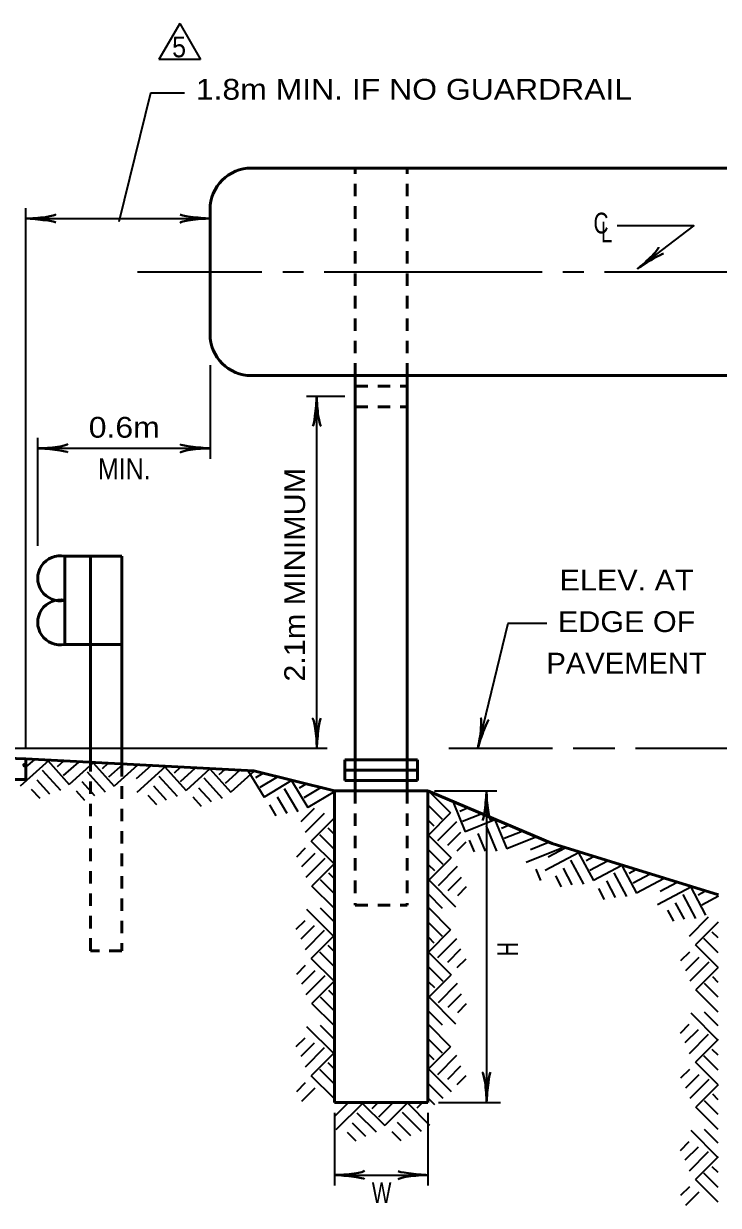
# Model space of a CAD drawing. Extents: x -27 to 828, y -12 to 532.
# Drawn here: x 138.5 to 218.8, y 94.8 to 231.4 of the extents above; entities that cross this region are included whole.
import ezdxf
from ezdxf.enums import TextEntityAlignment as Align

# ---------------------------------------------------------------- set-up
doc = ezdxf.new("R2010")
doc.units = 0
doc.header["$LTSCALE"] = 0.96
doc.linetypes.add('SHORT_DASHED', pattern=[2.7, 1.5, -1.2])
doc.layers.add('1', color=7, linetype='Continuous', lineweight=35)

msp = doc.modelspace()

# ---------------------------------------------------------------- linework, layer by layer
at = {"layer": '1'}
for p, q in [((156.5064, 231.4008), (154.1064, 227.2439)), ((156.5064, 231.4008), (158.9064, 227.2439)), ((158.9064, 227.2439), (154.1064, 227.2439)), ((138.7294, 147.6739), (138.7294, 210.0739)), ((138.7294, 208.8739), (160.008, 208.8739)), ((151.608, 202.7133), (166.008, 202.7133)), ((168.408, 202.7133), (170.808, 202.7133)), ((173.208, 202.7133), (198.408, 202.7133)), ((200.808, 202.7133), (203.208, 202.7133)), ((205.608, 202.7133), (230.808, 202.7133)), ((160.008, 191.9133), (160.008, 181.1133)), ((175.608, 188.3133), (171.1513, 188.3133)), ((172.3513, 147.6739), (172.3513, 188.3133)), ((140.1198, 171.0369), (140.1198, 183.5133)), ((140.1198, 182.3133), (160.008, 182.3133)), ((111.1513, 147.6739), (173.5513, 147.6739)), ((187.608, 147.6739), (199.608, 147.6739)), ((202.008, 147.6739), (206.808, 147.6739)), ((209.208, 147.6739), (221.208, 147.6739)), ((141.3633, 146.2314), (138.059, 143.2563)), ((139.6616, 146.3206), (138.7294, 145.4812)), ((141.2434, 146.2377), (143.7416, 143.4631)), ((140.6079, 145.1174), (142.7213, 142.7956)), ((143.0649, 146.1422), (142.3574, 145.4823)), ((144.7905, 146.0518), (143.0501, 144.4847)), ((146.4922, 145.9626), (143.7416, 143.4631)), ((145.8125, 144.9167), (147.902, 142.5962)), ((146.4922, 145.9626), (148.9223, 143.2637)), ((148.1939, 145.8734), (147.5381, 145.2829)), ((149.9195, 145.783), (148.2548, 144.284)), ((151.6212, 145.6938), (148.9223, 143.2637)), ((153.1551, 145.6134), (151.4903, 144.1145)), ((154.8567, 145.5242), (151.5525, 142.5491)), ((154.7369, 145.5305), (157.2351, 142.7559)), ((156.5584, 145.435), (155.8509, 144.7752)), ((158.284, 145.3446), (156.5436, 143.7775)), ((159.9857, 145.2554), (157.2351, 142.7559)), ((159.9857, 145.2554), (162.4158, 142.5565)), ((161.6874, 145.1662), (161.0316, 144.5757)), ((163.413, 145.0758), (161.7483, 143.5769)), ((165.1147, 144.9866), (162.4158, 142.5565)), ((164.3982, 145.0722), (166.2593, 141.9748)), ((139.9964, 143.9959), (141.4499, 142.3816)), ((145.201, 143.7952), (146.6545, 142.1809)), ((154.1014, 144.4102), (156.2148, 142.0884)), ((159.306, 144.2096), (161.3954, 141.889)), ((166.1062, 144.7338), (165.2858, 144.221)), ((167.7829, 144.3157), (165.7754, 143.1095)), ((169.4362, 143.9035), (166.2593, 141.9748)), ((169.4362, 143.9035), (171.3067, 140.7905)), ((171.0896, 143.4912), (170.3332, 143.0367)), ((139.3394, 142.9248), (140.3172, 141.8642)), ((144.5201, 142.7254), (145.4967, 141.6408)), ((152.8329, 142.2176), (153.8107, 141.157)), ((153.4899, 143.2887), (154.9434, 141.6744)), ((158.6945, 143.088), (160.148, 141.4737)), ((168.5695, 143.0065), (170.1777, 140.3299)), ((172.7663, 143.0732), (170.8461, 141.9194)), ((174.4197, 142.6609), (171.3067, 140.7905)), ((185.256, 142.7373), (187.824, 140.1693)), ((185.9784, 142.7385), (193.1784, 142.7385)), ((191.9784, 142.7385), (191.9784, 106.7385)), ((158.0136, 142.0182), (158.9901, 140.9336)), ((166.8826, 141.102), (167.6343, 139.851)), ((167.7552, 142.0223), (168.874, 140.1603)), ((185.256, 141.0333), (186.84, 139.4493)), ((188.1054, 141.4313), (189.504, 137.9696)), ((189.7844, 140.7186), (188.8939, 140.3405)), ((172.056, 140.6733), (170.52, 139.1373)), ((173.208, 140.1213), (171, 137.8893)), ((174.36, 139.5453), (171.72, 136.9053)), ((185.256, 137.6013), (187.824, 140.1693)), ((191.375, 140.0434), (189.2036, 139.1661)), ((192.9436, 139.3776), (189.504, 137.9696)), ((192.9436, 139.3776), (194.304, 136.0104)), ((174.36, 137.7213), (173.664, 138.3933)), ((185.256, 139.3053), (185.88, 138.6813)), ((186.336, 136.9773), (188.544, 139.1853)), ((187.488, 136.4253), (189.024, 137.9613)), ((191.9472, 138.6273), (193.1169, 135.7321)), ((194.5121, 138.7118), (193.6939, 138.3812)), ((196.1028, 138.0366), (194.0258, 137.1975)), ((174.36, 134.2893), (171.72, 136.9053)), ((174.36, 135.9933), (172.704, 137.6493)), ((185.256, 137.6013), (187.896, 134.9853)), ((188.592, 135.8013), (189.624, 136.8333)), ((189.9832, 137.0101), (190.5299, 135.6569)), ((190.989, 137.7825), (191.8027, 135.7685)), ((197.6713, 137.3708), (194.304, 136.0104)), ((199.1294, 136.7519), (197.0524, 135.9127)), ((171.024, 136.0893), (169.992, 135.0573)), ((172.128, 135.4653), (170.592, 133.9293)), ((185.256, 135.8973), (186.912, 134.2413)), ((200.6979, 136.0861), (196.5754, 134.4205)), ((202.6971, 135.6074), (198.7691, 133.5241)), ((201.0681, 136.1073), (199.0891, 135.0577)), ((202.5824, 135.6426), (204.3317, 132.3442)), ((173.28, 134.9133), (171.072, 132.7053)), ((174.36, 134.2893), (171.792, 131.7213)), ((185.256, 132.3453), (187.896, 134.9853)), ((185.256, 134.1693), (185.952, 133.4973)), ((186.408, 131.7693), (188.616, 134.0013)), ((201.6938, 134.7103), (203.1798, 131.9446)), ((204.3261, 135.1074), (203.4795, 134.6392)), ((205.9781, 134.6005), (203.9091, 133.5032)), ((207.6071, 134.1005), (204.3317, 132.3442)), ((207.6071, 134.1005), (209.3087, 130.8921)), ((174.36, 132.5853), (173.736, 133.2093)), ((187.56, 131.2173), (189.096, 132.7533)), ((197.6652, 133.6711), (198.2213, 132.34)), ((199.9306, 132.8915), (200.6214, 131.6251)), ((200.8281, 133.7709), (201.8459, 131.8518)), ((206.6937, 133.2511), (208.1568, 130.4925)), ((209.2361, 133.6006), (208.4565, 133.1871)), ((210.8881, 133.0936), (208.9091, 132.0441)), ((212.5171, 132.5937), (209.3087, 130.8921)), ((174.36, 129.1533), (171.792, 131.7213)), ((174.36, 130.8573), (172.776, 132.4413)), ((185.256, 132.4653), (188.4, 129.3213)), ((188.664, 130.6173), (189.672, 131.6493)), ((204.9076, 131.4394), (205.5914, 130.1501)), ((205.828, 132.3118), (206.8458, 130.3927)), ((215.6604, 131.6291), (211.7324, 129.5458)), ((214.0314, 132.129), (212.0524, 131.0794)), ((215.5457, 131.6643), (217.295, 128.3659)), ((217.2894, 131.1291), (216.4428, 130.6609)), ((185.256, 130.7613), (186.84, 129.1773)), ((213.7914, 129.7926), (214.8091, 127.8735)), ((214.6571, 130.7319), (216.143, 127.9663)), ((218.808, 130.5515), (216.8724, 129.5249)), ((174.36, 125.8653), (171.216, 129.0093)), ((174.36, 127.5693), (172.776, 129.1533)), ((185.256, 129.2253), (187.824, 126.6573)), ((212.8939, 128.9132), (213.5847, 127.6468)), ((170.952, 127.7133), (169.944, 126.6813)), ((172.056, 127.1133), (170.52, 125.5773)), ((185.256, 127.5213), (186.84, 125.9373)), ((217.608, 128.1213), (215.4, 125.8893)), ((218.76, 127.5453), (216.12, 124.9053)), ((173.208, 126.5613), (171, 124.3293)), ((174.36, 125.9853), (171.72, 123.3453)), ((185.256, 124.0893), (187.824, 126.6573)), ((185.256, 125.7933), (185.88, 125.1693)), ((186.336, 123.4653), (188.544, 125.6733)), ((218.76, 125.7213), (218.064, 126.3933)), ((174.36, 124.1613), (173.664, 124.8333)), ((187.488, 122.9133), (189.024, 124.4493)), ((218.76, 122.2893), (216.12, 124.9053)), ((218.76, 123.9933), (217.104, 125.6493)), ((174.36, 120.7293), (171.72, 123.3453)), ((174.36, 122.4333), (172.704, 124.0893)), ((185.256, 124.0893), (187.896, 121.4733)), ((188.592, 122.2893), (189.624, 123.3213)), ((215.424, 124.0893), (214.392, 123.0573)), ((216.528, 123.4653), (214.992, 121.9293)), ((171.024, 122.5293), (169.992, 121.4973)), ((172.128, 121.9053), (170.592, 120.3693)), ((185.256, 122.3853), (186.912, 120.7293)), ((217.68, 122.9133), (215.472, 120.7053)), ((218.76, 122.2893), (216.192, 119.7213)), ((173.28, 121.3533), (171.072, 119.1453)), ((174.36, 120.7293), (171.792, 118.1613)), ((185.256, 118.8333), (187.896, 121.4733)), ((185.256, 120.6573), (185.952, 119.9853)), ((186.408, 118.2573), (188.616, 120.4893)), ((218.76, 118.8573), (217.176, 120.4413)), ((218.76, 120.5853), (218.136, 121.2093)), ((174.36, 117.2973), (172.776, 118.8813)), ((174.36, 119.0253), (173.736, 119.6493)), ((185.256, 118.9533), (188.4, 115.8093)), ((187.56, 117.7053), (189.096, 119.2413)), ((218.76, 117.1533), (216.192, 119.7213)), ((174.36, 115.5933), (171.792, 118.1613)), ((188.664, 117.1053), (189.672, 118.1373)), ((185.256, 117.2493), (186.84, 115.6653)), ((218.76, 113.8653), (215.616, 117.0093)), ((218.76, 115.5693), (217.176, 117.1533)), ((174.36, 112.3053), (171.216, 115.4493)), ((174.36, 114.0093), (172.776, 115.5933)), ((185.256, 115.7133), (187.824, 113.1453)), ((215.352, 115.7133), (214.344, 114.6813)), ((216.456, 115.1133), (214.92, 113.5773)), ((170.952, 114.1533), (169.944, 113.1213)), ((172.056, 113.5533), (170.52, 112.0173)), ((185.256, 114.0093), (186.84, 112.4253)), ((217.608, 114.5613), (215.4, 112.3293)), ((218.76, 113.9853), (216.12, 111.3453)), ((173.208, 113.0013), (171, 110.7693)), ((174.36, 112.4253), (171.72, 109.7853)), ((185.256, 110.5773), (187.824, 113.1453)), ((185.256, 112.2813), (185.88, 111.6573)), ((186.336, 109.9533), (188.544, 112.1613)), ((218.76, 110.4333), (217.104, 112.0893)), ((218.76, 112.1613), (218.064, 112.8333)), ((174.36, 110.6013), (173.664, 111.2733)), ((187.488, 109.4013), (189.024, 110.9373)), ((218.76, 108.7293), (216.12, 111.3453)), ((174.36, 107.1693), (171.72, 109.7853)), ((174.36, 108.8733), (172.704, 110.5293)), ((185.256, 110.5773), (187.896, 107.9613)), ((188.592, 108.7773), (189.624, 109.8093)), ((215.424, 110.5293), (214.392, 109.4973)), ((216.528, 109.9053), (214.992, 108.3693)), ((217.68, 109.3533), (215.472, 107.1453)), ((171.024, 108.9693), (169.992, 107.9373)), ((172.128, 108.3453), (170.592, 106.8093)), ((185.256, 108.8733), (186.912, 107.2173)), ((218.76, 108.7293), (216.192, 106.1613)), ((175.992, 106.6653), (174.408, 105.0813)), ((177.696, 106.6653), (174.552, 103.5213)), ((177.576, 106.6653), (180.216, 104.0253)), ((179.4, 106.6653), (178.728, 105.9693)), ((181.128, 106.6653), (179.472, 105.0093)), ((182.832, 106.6653), (180.216, 104.0253)), ((182.832, 106.6653), (185.4, 104.0973)), ((184.536, 106.6653), (183.912, 106.0413)), ((185.256, 107.1453), (185.952, 106.4733)), ((186.408, 106.7133), (193.608, 106.7133)), ((218.76, 105.2973), (217.176, 106.8813)), ((218.76, 107.0253), (218.136, 107.6493)), ((174.408, 105.5133), (174.408, 97.1133)), ((177, 105.5133), (179.232, 103.3053)), ((182.208, 105.5853), (184.416, 103.3773)), ((185.208, 105.5133), (185.208, 97.1133)), ((218.76, 103.5933), (216.192, 106.1613)), ((176.448, 104.3613), (177.984, 102.8253)), ((181.656, 104.4333), (183.192, 102.8973)), ((175.848, 103.2573), (176.88, 102.2493)), ((181.032, 103.3293), (182.064, 102.2973)), ((218.76, 100.3053), (215.616, 103.4493)), ((218.76, 102.0093), (217.176, 103.5933)), ((215.352, 102.1533), (214.344, 101.1213)), ((216.456, 101.5533), (214.92, 100.0173)), ((217.608, 101.0013), (215.4, 98.7693)), ((218.76, 100.4253), (216.12, 97.7853)), ((218.76, 96.8733), (217.104, 98.5293)), ((218.76, 98.6013), (218.064, 99.2733)), ((174.408, 98.3133), (185.208, 98.3133)), ((218.76, 95.1693), (216.12, 97.7853)), ((215.424, 96.9693), (214.392, 95.9373)), ((216.528, 96.3453), (214.992, 94.8093))]:
    msp.add_line(p, q, dxfattribs=at)
at = {"layer": '1', "lineweight": 53}
for p, q in [((164.808, 214.7133), (239.208, 214.7133)), ((160.008, 209.9133), (160.008, 195.5133)), ((164.808, 190.7133), (239.208, 190.7133)), ((176.808, 190.7133), (176.808, 142.7133)), ((182.808, 190.7133), (182.808, 142.7133)), ((149.808, 169.8369), (143.208, 169.8369)), ((143.208, 169.8369), (143.208, 159.6369)), ((146.208, 146.0256), (146.208, 169.8369)), ((149.808, 145.8369), (149.808, 169.8369)), ((149.808, 159.6369), (143.208, 159.6369)), ((138.7294, 146.4175), (165.0932, 145.0358)), ((175.608, 146.3133), (184.008, 146.3133)), ((175.608, 146.3133), (175.608, 143.9133)), ((184.008, 146.3133), (184.008, 143.9133)), ((138.7294, 145.7955), (138.7132, 145.8171)), ((165.0932, 145.0358), (174.408, 142.7133)), ((175.608, 145.1133), (184.008, 145.1133)), ((175.608, 143.9133), (184.008, 143.9133)), ((174.408, 142.7133), (185.208, 142.7133)), ((174.408, 142.7133), (174.408, 106.7133)), ((185.208, 142.7133), (185.208, 106.7133)), ((185.208, 142.7133), (199.5679, 136.6179)), ((199.5679, 136.6179), (218.808, 130.7133)), ((174.408, 106.7133), (185.208, 106.7133))]:
    msp.add_line(p, q, dxfattribs=at)
at = {"layer": '1', "linetype": 'SHORT_DASHED', "lineweight": 53}
for p, q in [((176.808, 190.7133), (176.808, 214.7133)), ((182.808, 190.7133), (182.808, 214.7133)), ((176.808, 189.5133), (182.808, 189.5133)), ((176.808, 187.1133), (182.808, 187.1133)), ((176.808, 142.7133), (176.808, 129.5133)), ((182.808, 142.7133), (182.808, 129.5133)), ((176.808, 129.5133), (182.808, 129.5133))]:
    msp.add_line(p, q, dxfattribs=at)
at = {"layer": '1'}
for points in [[(149.5078, 208.5399), (153.1546, 223.3926), (157.062, 223.3926)], [(209.4202, 203.0679), (215.9325, 208.0188), (207.0758, 208.0188)], [(190.9662, 147.6739), (194.4785, 162.0974), (198.9511, 162.0974)]]:
    msp.add_lwpolyline(points, dxfattribs=at)
at = {"layer": '1', "lineweight": 53}
msp.add_lwpolyline([(66.7294, 144.0175), (102.7513, 144.0175), (102.7513, 147.6739), (138.7294, 146.4175), (138.7294, 144.0175), (102.7513, 144.0175), (102.7513, 147.6739), (138.7294, 146.4175), (138.7294, 144.0175), (102.7513, 144.0175)], dxfattribs=at)
at = {"layer": '1', "linetype": 'SHORT_DASHED', "lineweight": 53}
msp.add_lwpolyline([(149.808, 145.8369), (149.808, 124.2369), (146.208, 124.2369), (146.208, 146.0256)], dxfattribs=at)
at = {"layer": '1', "lineweight": 53}
for centre, radius, start, end in [((164.808, 209.9133), 4.8, 90, 180), ((164.808, 195.5133), 4.8, 180, 270), ((142.6946, 167.2869), 2.6012, 78.61588, 281.38413), ((142.6946, 162.1869), 2.6012, 78.61588, 281.38413)]:
    msp.add_arc(centre, radius, start, end, dxfattribs=at)
at = {"layer": '1', "lineweight": 40}
for centre, major_axis, ratio, start_param, end_param in [((140.0388, 209.2055), (-2.1428, -0.1874), 0.122415, 0.89635335, 3.14159265), ((158.6634, 209.1278), (2.1077, -0.2108), 0.07063, 3.14071475, 5.41810995), ((140.074, 208.62), (-2.1077, 0.2108), 0.07063, 3.14071475, 5.41810995), ((158.6986, 208.5423), (2.1428, 0.1874), 0.122415, 0.89635335, 3.14159265), ((210.2619, 204.1243), (-1.5924, -1.446), 0.122415, 0.89635335, 3.14159265), ((210.6443, 203.6795), (-1.8055, -1.1078), 0.07063, 3.14071475, 5.41810995), ((172.0974, 186.9687), (0.2108, 2.1077), 0.07063, 3.14071475, 5.41810995), ((172.6829, 187.0039), (-0.1874, 2.1428), 0.122415, 0.89635335, 3.14159265), ((141.4644, 182.0594), (-2.1077, 0.2108), 0.07063, 3.14071475, 5.41810995), ((141.4292, 182.6449), (-2.1428, -0.1874), 0.122415, 0.89635335, 3.14159265), ((158.6986, 181.9817), (2.1428, 0.1874), 0.122415, 0.89635335, 3.14159265), ((158.6634, 182.5672), (2.1077, -0.2108), 0.07063, 3.14071475, 5.41810995), ((172.0197, 148.9833), (0.1874, -2.1428), 0.122415, 0.89635335, 3.14159265), ((172.6052, 149.0185), (-0.2108, -2.1077), 0.07063, 3.14071475, 5.41810995), ((190.9539, 149.0246), (-0.3249, -2.1263), 0.122415, 0.89635335, 3.14159265), ((191.531, 148.9202), (0.7035, 1.998), 0.07063, 6.28230741, 8.55970261), ((191.7245, 141.3939), (0.2108, 2.1077), 0.07063, 3.14071475, 5.41810995), ((192.31, 141.4291), (-0.1874, 2.1428), 0.122415, 0.89635335, 3.14159265), ((191.6468, 108.0479), (0.1874, -2.1428), 0.122415, 0.89635335, 3.14159265), ((191.6468, 108.0479), (0.1874, -2.1428), 0.122415, 0.89635335, 3.14159265), ((192.2323, 108.0831), (-0.2108, -2.1077), 0.07063, 3.14071475, 5.41810995), ((192.2323, 108.0831), (-0.2108, -2.1077), 0.07063, 3.14071475, 5.41810995), ((175.7174, 98.6449), (-2.1428, -0.1874), 0.122415, 0.89635335, 3.14159265), ((175.7174, 98.6449), (-2.1428, -0.1874), 0.122415, 0.89635335, 3.14159265), ((183.8634, 98.5672), (2.1077, -0.2108), 0.07063, 3.14071475, 5.41810995), ((183.8634, 98.5672), (2.1077, -0.2108), 0.07063, 3.14071475, 5.41810995), ((175.7526, 98.0594), (-2.1077, 0.2108), 0.07063, 3.14071475, 5.41810995), ((175.7526, 98.0594), (-2.1077, 0.2108), 0.07063, 3.14071475, 5.41810995), ((183.8986, 97.9817), (2.1428, 0.1874), 0.122415, 0.89635335, 3.14159265), ((183.8986, 97.9817), (2.1428, 0.1874), 0.122415, 0.89635335, 3.14159265)]:
    msp.add_ellipse(centre, major_axis=major_axis, ratio=ratio, start_param=start_param, end_param=end_param, dxfattribs=at)
at = {"layer": '1', "lineweight": 53}
msp.add_spline([(138.7294, 145.7451), (138.4732, 145.7451), (138.4972, 145.6491), (138.6412, 145.5771), (138.7294, 145.5595)], degree=3, dxfattribs=at)

# ---------------------------------------------------------------- texts
at = {"layer": '1'}
for s, width, p in [('5', 0.9, (155.6296, 227.511)), ('1.8m MIN. IF NO GUARDRAIL', 1.15, (158.3644, 222.6108)), ('C', 0.75, (204.3402, 207.1485)), ('L', 0.75, (205.191, 206.1272)), ('W', 0.75, (178.7104, 95.0796))]:
    msp.add_text(s, height=2.4, dxfattribs=dict(at, width=width)).set_placement(p)
for s, width, p in [('0.6m', 1.15, (150.0939, 183.5427)), ('MIN.', 0.9, (150.0938, 178.7427)), ('ELEV. AT', 1.1, (208.1701, 165.88)), ('EDGE OF', 1.1, (208.1701, 161.08)), ('PAVEMENT', 1.05, (208.17, 156.28))]:
    msp.add_text(s, height=2.4, dxfattribs=dict(at, width=width)).set_placement(p, align=Align.CENTER)
for s, width, p in [('2.1m MINIMUM', 1.1, (170.9947, 155.3409)), ('H', 0.7, (195.6258, 123.6146))]:
    msp.add_text(s, height=2.4, rotation=90, dxfattribs=dict(at, width=width)).set_placement(p)

doc.saveas('drawing.dxf')
